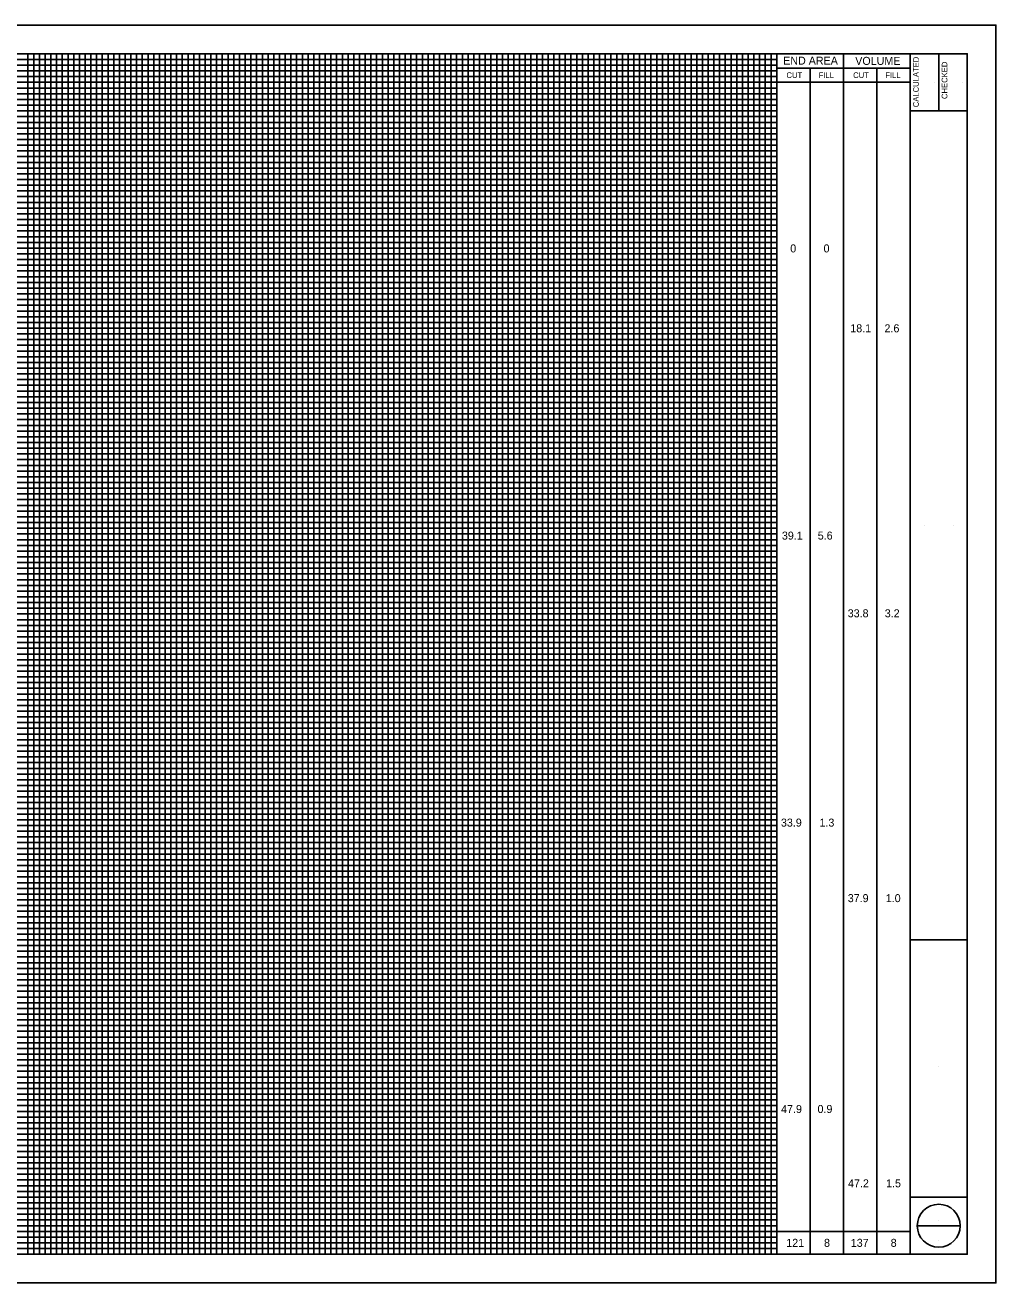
# Model space of a CAD drawing. Extents: x 2267521 to 2268201, y 655023 to 655463.
# Drawn here: x 2267861.3 to 2268201, y 655023.4 to 655463.4 of the extents above; entities that cross this region are included whole.
import ezdxf

# ---------------------------------------------------------------- set-up
doc = ezdxf.new("R2010")
doc.units = 0
for name, color, linetype in [('SH_Border', 7, 'Continuous'), ('SH_Cut_Line', 7, 'Continuous'), ('SH_Data', 7, 'Continuous'), ('SH_Major_Grid_Line', 7, 'Continuous'), ('SH_Masking', 7, 'Continuous'), ('SH_Minor_Grid_Line', 7, 'Continuous'), ('SH_Text', 7, 'Continuous')]:
    doc.layers.add(name, color=color, linetype=linetype)

msp = doc.modelspace()

# ---------------------------------------------------------------- linework, layer by layer
at = {"layer": 'SH_Border'}
for p, q in [((2268170.96, 655033.36), (2268170.96, 655453.36)), ((2268180.96, 655453.36), (2268180.96, 655433.36)), ((2268170.96, 655433.36), (2268190.96, 655433.36)), ((2268170.96, 655143.36), (2268190.96, 655143.36)), ((2268170.96, 655053.36), (2268190.96, 655053.36))]:
    msp.add_line(p, q, dxfattribs=at)
msp.add_lwpolyline([(2267560.96, 655453.36), (2268190.96, 655453.36), (2268190.96, 655033.36), (2267560.96, 655033.36)], close=True, dxfattribs=at)
at = {"layer": 'SH_Cut_Line'}
msp.add_lwpolyline([(2267520.96, 655023.36), (2268200.96, 655023.36), (2268200.96, 655463.36), (2267520.96, 655463.36)], close=True, dxfattribs=at)
at = {"layer": 'SH_Data'}
for p, q in [((2268124.29, 655033.36), (2268124.29, 655453.36)), ((2268147.63, 655033.36), (2268147.63, 655453.36)), ((2268124.29, 655448.36), (2268170.96, 655448.36)), ((2268135.96, 655033.36), (2268135.96, 655448.36)), ((2268159.3, 655033.36), (2268159.3, 655448.36)), ((2268124.29, 655443.36), (2268170.96, 655443.36)), ((2268179.36, 655443.43), (2268179.36, 655443.43)), ((2268189.36, 655443.43), (2268189.36, 655443.43)), ((2268175.96, 655288.36), (2268175.96, 655288.36)), ((2268186, 655288.36), (2268186, 655288.36)), ((2268180.96, 655099.2), (2268180.96, 655099.2)), ((2268124.29, 655041.36), (2268170.96, 655041.36)), ((2268173.46, 655043.36), (2268188.46, 655043.36)), ((2268180.96, 655045.06), (2268180.96, 655045.06)), ((2268130.13, 655037.36), (2268130.13, 655037.36)), ((2268141.8, 655037.36), (2268141.8, 655037.36)), ((2268153.46, 655037.36), (2268153.46, 655037.36)), ((2268165.13, 655037.36), (2268165.13, 655037.36)), ((2268180.96, 655038.26), (2268180.96, 655038.26))]:
    msp.add_line(p, q, dxfattribs=at)
msp.add_circle((2268180.96, 655043.36), 7.5, dxfattribs=at)
at = {"layer": 'SH_Major_Grid_Line'}
for p, q in [((2267864.29, 655033.36), (2267864.29, 655453.36)), ((2267884.29, 655033.36), (2267884.29, 655453.36)), ((2267904.29, 655033.36), (2267904.29, 655453.36)), ((2267924.29, 655033.36), (2267924.29, 655453.36)), ((2267944.29, 655033.36), (2267944.29, 655453.36)), ((2267964.29, 655033.36), (2267964.29, 655453.36)), ((2267984.29, 655033.36), (2267984.29, 655453.36)), ((2268004.29, 655033.36), (2268004.29, 655453.36)), ((2268024.29, 655033.36), (2268024.29, 655453.36)), ((2268044.29, 655033.36), (2268044.29, 655453.36)), ((2268064.29, 655033.36), (2268064.29, 655453.36)), ((2268084.29, 655033.36), (2268084.29, 655453.36)), ((2268104.29, 655033.36), (2268104.29, 655453.36)), ((2267584.29, 655433.36), (2268124.29, 655433.36)), ((2267584.29, 655413.36), (2268124.29, 655413.36)), ((2267584.29, 655393.36), (2268124.29, 655393.36)), ((2267584.29, 655373.36), (2268124.29, 655373.36)), ((2267584.29, 655353.36), (2268124.29, 655353.36)), ((2267584.29, 655333.36), (2268124.29, 655333.36)), ((2267584.29, 655313.36), (2268124.29, 655313.36)), ((2267584.29, 655293.36), (2268124.29, 655293.36)), ((2267584.29, 655273.36), (2268124.29, 655273.36)), ((2267584.29, 655253.36), (2268124.29, 655253.36)), ((2267584.29, 655233.36), (2268124.29, 655233.36)), ((2267584.29, 655213.36), (2268124.29, 655213.36)), ((2267584.29, 655193.36), (2268124.29, 655193.36)), ((2267584.29, 655173.36), (2268124.29, 655173.36)), ((2267584.29, 655153.36), (2268124.29, 655153.36)), ((2267584.29, 655133.36), (2268124.29, 655133.36)), ((2267584.29, 655113.36), (2268124.29, 655113.36)), ((2267584.29, 655093.36), (2268124.29, 655093.36)), ((2267584.29, 655073.36), (2268124.29, 655073.36)), ((2267584.29, 655053.36), (2268124.29, 655053.36))]:
    msp.add_line(p, q, dxfattribs=at)
at = {"layer": 'SH_Masking'}
msp.add_lwpolyline([(2267584.29, 655033.36), (2268124.29, 655033.36), (2268124.29, 655453.36), (2267584.29, 655453.36)], close=True, dxfattribs=at)
at = {"layer": 'SH_Minor_Grid_Line'}
for p, q in [((2267584.29, 655451.36), (2268124.29, 655451.36)), ((2267862.29, 655033.36), (2267862.29, 655453.36)), ((2267866.29, 655033.36), (2267866.29, 655453.36)), ((2267868.29, 655033.36), (2267868.29, 655453.36)), ((2267870.29, 655033.36), (2267870.29, 655453.36)), ((2267872.29, 655033.36), (2267872.29, 655453.36)), ((2267874.29, 655033.36), (2267874.29, 655453.36)), ((2267876.29, 655033.36), (2267876.29, 655453.36)), ((2267878.29, 655033.36), (2267878.29, 655453.36)), ((2267880.29, 655033.36), (2267880.29, 655453.36)), ((2267882.29, 655033.36), (2267882.29, 655453.36)), ((2267886.29, 655033.36), (2267886.29, 655453.36)), ((2267888.29, 655033.36), (2267888.29, 655453.36)), ((2267890.29, 655033.36), (2267890.29, 655453.36)), ((2267892.29, 655033.36), (2267892.29, 655453.36)), ((2267894.29, 655033.36), (2267894.29, 655453.36)), ((2267896.29, 655033.36), (2267896.29, 655453.36)), ((2267898.29, 655033.36), (2267898.29, 655453.36)), ((2267900.29, 655033.36), (2267900.29, 655453.36)), ((2267902.29, 655033.36), (2267902.29, 655453.36)), ((2267906.29, 655033.36), (2267906.29, 655453.36)), ((2267908.29, 655033.36), (2267908.29, 655453.36)), ((2267910.29, 655033.36), (2267910.29, 655453.36)), ((2267912.29, 655033.36), (2267912.29, 655453.36)), ((2267914.29, 655033.36), (2267914.29, 655453.36)), ((2267916.29, 655033.36), (2267916.29, 655453.36)), ((2267918.29, 655033.36), (2267918.29, 655453.36)), ((2267920.29, 655033.36), (2267920.29, 655453.36)), ((2267922.29, 655033.36), (2267922.29, 655453.36)), ((2267926.29, 655033.36), (2267926.29, 655453.36)), ((2267928.29, 655033.36), (2267928.29, 655453.36)), ((2267930.29, 655033.36), (2267930.29, 655453.36)), ((2267932.29, 655033.36), (2267932.29, 655453.36)), ((2267934.29, 655033.36), (2267934.29, 655453.36)), ((2267936.29, 655033.36), (2267936.29, 655453.36)), ((2267938.29, 655033.36), (2267938.29, 655453.36)), ((2267940.29, 655033.36), (2267940.29, 655453.36)), ((2267942.29, 655033.36), (2267942.29, 655453.36)), ((2267946.29, 655033.36), (2267946.29, 655453.36)), ((2267948.29, 655033.36), (2267948.29, 655453.36)), ((2267950.29, 655033.36), (2267950.29, 655453.36)), ((2267952.29, 655033.36), (2267952.29, 655453.36)), ((2267954.29, 655033.36), (2267954.29, 655453.36)), ((2267956.29, 655033.36), (2267956.29, 655453.36)), ((2267958.29, 655033.36), (2267958.29, 655453.36)), ((2267960.29, 655033.36), (2267960.29, 655453.36)), ((2267962.29, 655033.36), (2267962.29, 655453.36)), ((2267966.29, 655033.36), (2267966.29, 655453.36)), ((2267968.29, 655033.36), (2267968.29, 655453.36)), ((2267970.29, 655033.36), (2267970.29, 655453.36)), ((2267972.29, 655033.36), (2267972.29, 655453.36)), ((2267974.29, 655033.36), (2267974.29, 655453.36)), ((2267976.29, 655033.36), (2267976.29, 655453.36)), ((2267978.29, 655033.36), (2267978.29, 655453.36)), ((2267980.29, 655033.36), (2267980.29, 655453.36)), ((2267982.29, 655033.36), (2267982.29, 655453.36)), ((2267986.29, 655033.36), (2267986.29, 655453.36)), ((2267988.29, 655033.36), (2267988.29, 655453.36)), ((2267990.29, 655033.36), (2267990.29, 655453.36)), ((2267992.29, 655033.36), (2267992.29, 655453.36)), ((2267994.29, 655033.36), (2267994.29, 655453.36)), ((2267996.29, 655033.36), (2267996.29, 655453.36)), ((2267998.29, 655033.36), (2267998.29, 655453.36)), ((2268000.29, 655033.36), (2268000.29, 655453.36)), ((2268002.29, 655033.36), (2268002.29, 655453.36)), ((2268006.29, 655033.36), (2268006.29, 655453.36)), ((2268008.29, 655033.36), (2268008.29, 655453.36)), ((2268010.29, 655033.36), (2268010.29, 655453.36)), ((2268012.29, 655033.36), (2268012.29, 655453.36)), ((2268014.29, 655033.36), (2268014.29, 655453.36)), ((2268016.29, 655033.36), (2268016.29, 655453.36)), ((2268018.29, 655033.36), (2268018.29, 655453.36)), ((2268020.29, 655033.36), (2268020.29, 655453.36)), ((2268022.29, 655033.36), (2268022.29, 655453.36)), ((2268026.29, 655033.36), (2268026.29, 655453.36)), ((2268028.29, 655033.36), (2268028.29, 655453.36)), ((2268030.29, 655033.36), (2268030.29, 655453.36)), ((2268032.29, 655033.36), (2268032.29, 655453.36)), ((2268034.29, 655033.36), (2268034.29, 655453.36)), ((2268036.29, 655033.36), (2268036.29, 655453.36)), ((2268038.29, 655033.36), (2268038.29, 655453.36)), ((2268040.29, 655033.36), (2268040.29, 655453.36)), ((2268042.29, 655033.36), (2268042.29, 655453.36)), ((2268046.29, 655033.36), (2268046.29, 655453.36)), ((2268048.29, 655033.36), (2268048.29, 655453.36)), ((2268050.29, 655033.36), (2268050.29, 655453.36)), ((2268052.29, 655033.36), (2268052.29, 655453.36)), ((2268054.29, 655033.36), (2268054.29, 655453.36)), ((2268056.29, 655033.36), (2268056.29, 655453.36)), ((2268058.29, 655033.36), (2268058.29, 655453.36)), ((2268060.29, 655033.36), (2268060.29, 655453.36)), ((2268062.29, 655033.36), (2268062.29, 655453.36)), ((2268066.29, 655033.36), (2268066.29, 655453.36)), ((2268068.29, 655033.36), (2268068.29, 655453.36)), ((2268070.29, 655033.36), (2268070.29, 655453.36)), ((2268072.29, 655033.36), (2268072.29, 655453.36)), ((2268074.29, 655033.36), (2268074.29, 655453.36)), ((2268076.29, 655033.36), (2268076.29, 655453.36)), ((2268078.29, 655033.36), (2268078.29, 655453.36)), ((2268080.29, 655033.36), (2268080.29, 655453.36)), ((2268082.29, 655033.36), (2268082.29, 655453.36)), ((2268086.29, 655033.36), (2268086.29, 655453.36)), ((2268088.29, 655033.36), (2268088.29, 655453.36)), ((2268090.29, 655033.36), (2268090.29, 655453.36)), ((2268092.29, 655033.36), (2268092.29, 655453.36)), ((2268094.29, 655033.36), (2268094.29, 655453.36)), ((2268096.29, 655033.36), (2268096.29, 655453.36)), ((2268098.29, 655033.36), (2268098.29, 655453.36)), ((2268100.29, 655033.36), (2268100.29, 655453.36)), ((2268102.29, 655033.36), (2268102.29, 655453.36)), ((2268106.29, 655033.36), (2268106.29, 655453.36)), ((2268108.29, 655033.36), (2268108.29, 655453.36)), ((2268110.29, 655033.36), (2268110.29, 655453.36)), ((2268112.29, 655033.36), (2268112.29, 655453.36)), ((2268114.29, 655033.36), (2268114.29, 655453.36)), ((2268116.29, 655033.36), (2268116.29, 655453.36)), ((2268118.29, 655033.36), (2268118.29, 655453.36)), ((2268120.29, 655033.36), (2268120.29, 655453.36)), ((2268122.29, 655033.36), (2268122.29, 655453.36)), ((2267584.29, 655449.36), (2268124.29, 655449.36)), ((2267584.29, 655447.36), (2268124.29, 655447.36)), ((2267584.29, 655445.36), (2268124.29, 655445.36)), ((2267584.29, 655443.36), (2268124.29, 655443.36)), ((2267584.29, 655441.36), (2268124.29, 655441.36)), ((2267584.29, 655439.36), (2268124.29, 655439.36)), ((2267584.29, 655437.36), (2268124.29, 655437.36)), ((2267584.29, 655435.36), (2268124.29, 655435.36)), ((2267584.29, 655431.36), (2268124.29, 655431.36)), ((2267584.29, 655429.36), (2268124.29, 655429.36)), ((2267584.29, 655427.36), (2268124.29, 655427.36)), ((2267584.29, 655425.36), (2268124.29, 655425.36)), ((2267584.29, 655423.36), (2268124.29, 655423.36)), ((2267584.29, 655421.36), (2268124.29, 655421.36)), ((2267584.29, 655419.36), (2268124.29, 655419.36)), ((2267584.29, 655417.36), (2268124.29, 655417.36)), ((2267584.29, 655415.36), (2268124.29, 655415.36)), ((2267584.29, 655411.36), (2268124.29, 655411.36)), ((2267584.29, 655409.36), (2268124.29, 655409.36)), ((2267584.29, 655407.36), (2268124.29, 655407.36)), ((2267584.29, 655405.36), (2268124.29, 655405.36)), ((2267584.29, 655403.36), (2268124.29, 655403.36)), ((2267584.29, 655401.36), (2268124.29, 655401.36)), ((2267584.29, 655399.36), (2268124.29, 655399.36)), ((2267584.29, 655397.36), (2268124.29, 655397.36)), ((2267584.29, 655395.36), (2268124.29, 655395.36)), ((2267584.29, 655391.36), (2268124.29, 655391.36)), ((2267584.29, 655389.36), (2268124.29, 655389.36)), ((2267584.29, 655387.36), (2268124.29, 655387.36)), ((2267584.29, 655385.36), (2268124.29, 655385.36)), ((2267584.29, 655383.36), (2268124.29, 655383.36)), ((2267584.29, 655381.36), (2268124.29, 655381.36)), ((2267584.29, 655379.36), (2268124.29, 655379.36)), ((2267584.29, 655377.36), (2268124.29, 655377.36)), ((2267584.29, 655375.36), (2268124.29, 655375.36)), ((2267584.29, 655371.36), (2268124.29, 655371.36)), ((2267584.29, 655369.36), (2268124.29, 655369.36)), ((2267584.29, 655367.36), (2268124.29, 655367.36)), ((2267584.29, 655365.36), (2268124.29, 655365.36)), ((2267584.29, 655363.36), (2268124.29, 655363.36)), ((2267584.29, 655361.36), (2268124.29, 655361.36)), ((2267584.29, 655359.36), (2268124.29, 655359.36)), ((2267584.29, 655357.36), (2268124.29, 655357.36)), ((2267584.29, 655355.36), (2268124.29, 655355.36)), ((2267584.29, 655351.36), (2268124.29, 655351.36)), ((2267584.29, 655349.36), (2268124.29, 655349.36)), ((2267584.29, 655347.36), (2268124.29, 655347.36)), ((2267584.29, 655345.36), (2268124.29, 655345.36)), ((2267584.29, 655343.36), (2268124.29, 655343.36)), ((2267584.29, 655341.36), (2268124.29, 655341.36)), ((2267584.29, 655339.36), (2268124.29, 655339.36)), ((2267584.29, 655337.36), (2268124.29, 655337.36)), ((2267584.29, 655335.36), (2268124.29, 655335.36)), ((2267584.29, 655331.36), (2268124.29, 655331.36)), ((2267584.29, 655329.36), (2268124.29, 655329.36)), ((2267584.29, 655327.36), (2268124.29, 655327.36)), ((2267584.29, 655325.36), (2268124.29, 655325.36)), ((2267584.29, 655323.36), (2268124.29, 655323.36)), ((2267584.29, 655321.36), (2268124.29, 655321.36)), ((2267584.29, 655319.36), (2268124.29, 655319.36)), ((2267584.29, 655317.36), (2268124.29, 655317.36)), ((2267584.29, 655315.36), (2268124.29, 655315.36)), ((2267584.29, 655311.36), (2268124.29, 655311.36)), ((2267584.29, 655309.36), (2268124.29, 655309.36)), ((2267584.29, 655307.36), (2268124.29, 655307.36)), ((2267584.29, 655305.36), (2268124.29, 655305.36)), ((2267584.29, 655303.36), (2268124.29, 655303.36)), ((2267584.29, 655301.36), (2268124.29, 655301.36)), ((2267584.29, 655299.36), (2268124.29, 655299.36)), ((2267584.29, 655297.36), (2268124.29, 655297.36)), ((2267584.29, 655295.36), (2268124.29, 655295.36)), ((2267584.29, 655291.36), (2268124.29, 655291.36)), ((2267584.29, 655289.36), (2268124.29, 655289.36)), ((2267584.29, 655287.36), (2268124.29, 655287.36)), ((2267584.29, 655285.36), (2268124.29, 655285.36)), ((2267584.29, 655283.36), (2268124.29, 655283.36)), ((2267584.29, 655281.36), (2268124.29, 655281.36)), ((2267584.29, 655279.36), (2268124.29, 655279.36)), ((2267584.29, 655277.36), (2268124.29, 655277.36)), ((2267584.29, 655275.36), (2268124.29, 655275.36)), ((2267584.29, 655271.36), (2268124.29, 655271.36)), ((2267584.29, 655269.36), (2268124.29, 655269.36)), ((2267584.29, 655267.36), (2268124.29, 655267.36)), ((2267584.29, 655265.36), (2268124.29, 655265.36)), ((2267584.29, 655263.36), (2268124.29, 655263.36)), ((2267584.29, 655261.36), (2268124.29, 655261.36)), ((2267584.29, 655259.36), (2268124.29, 655259.36)), ((2267584.29, 655257.36), (2268124.29, 655257.36)), ((2267584.29, 655255.36), (2268124.29, 655255.36)), ((2267584.29, 655251.36), (2268124.29, 655251.36)), ((2267584.29, 655249.36), (2268124.29, 655249.36)), ((2267584.29, 655247.36), (2268124.29, 655247.36)), ((2267584.29, 655245.36), (2268124.29, 655245.36)), ((2267584.29, 655243.36), (2268124.29, 655243.36)), ((2267584.29, 655241.36), (2268124.29, 655241.36)), ((2267584.29, 655239.36), (2268124.29, 655239.36)), ((2267584.29, 655237.36), (2268124.29, 655237.36)), ((2267584.29, 655235.36), (2268124.29, 655235.36)), ((2267584.29, 655231.36), (2268124.29, 655231.36)), ((2267584.29, 655229.36), (2268124.29, 655229.36)), ((2267584.29, 655227.36), (2268124.29, 655227.36)), ((2267584.29, 655225.36), (2268124.29, 655225.36)), ((2267584.29, 655223.36), (2268124.29, 655223.36)), ((2267584.29, 655221.36), (2268124.29, 655221.36)), ((2267584.29, 655219.36), (2268124.29, 655219.36)), ((2267584.29, 655217.36), (2268124.29, 655217.36)), ((2267584.29, 655215.36), (2268124.29, 655215.36)), ((2267584.29, 655211.36), (2268124.29, 655211.36)), ((2267584.29, 655209.36), (2268124.29, 655209.36)), ((2267584.29, 655207.36), (2268124.29, 655207.36)), ((2267584.29, 655205.36), (2268124.29, 655205.36)), ((2267584.29, 655203.36), (2268124.29, 655203.36)), ((2267584.29, 655201.36), (2268124.29, 655201.36)), ((2267584.29, 655199.36), (2268124.29, 655199.36)), ((2267584.29, 655197.36), (2268124.29, 655197.36)), ((2267584.29, 655195.36), (2268124.29, 655195.36)), ((2267584.29, 655191.36), (2268124.29, 655191.36)), ((2267584.29, 655189.36), (2268124.29, 655189.36)), ((2267584.29, 655187.36), (2268124.29, 655187.36)), ((2267584.29, 655185.36), (2268124.29, 655185.36)), ((2267584.29, 655183.36), (2268124.29, 655183.36)), ((2267584.29, 655181.36), (2268124.29, 655181.36)), ((2267584.29, 655179.36), (2268124.29, 655179.36)), ((2267584.29, 655177.36), (2268124.29, 655177.36)), ((2267584.29, 655175.36), (2268124.29, 655175.36)), ((2267584.29, 655171.36), (2268124.29, 655171.36)), ((2267584.29, 655169.36), (2268124.29, 655169.36)), ((2267584.29, 655167.36), (2268124.29, 655167.36)), ((2267584.29, 655165.36), (2268124.29, 655165.36)), ((2267584.29, 655163.36), (2268124.29, 655163.36)), ((2267584.29, 655161.36), (2268124.29, 655161.36)), ((2267584.29, 655159.36), (2268124.29, 655159.36)), ((2267584.29, 655157.36), (2268124.29, 655157.36)), ((2267584.29, 655155.36), (2268124.29, 655155.36)), ((2267584.29, 655151.36), (2268124.29, 655151.36)), ((2267584.29, 655149.36), (2268124.29, 655149.36)), ((2267584.29, 655147.36), (2268124.29, 655147.36)), ((2267584.29, 655145.36), (2268124.29, 655145.36)), ((2267584.29, 655143.36), (2268124.29, 655143.36)), ((2267584.29, 655141.36), (2268124.29, 655141.36)), ((2267584.29, 655139.36), (2268124.29, 655139.36)), ((2267584.29, 655137.36), (2268124.29, 655137.36)), ((2267584.29, 655135.36), (2268124.29, 655135.36)), ((2267584.29, 655131.36), (2268124.29, 655131.36)), ((2267584.29, 655129.36), (2268124.29, 655129.36)), ((2267584.29, 655127.36), (2268124.29, 655127.36)), ((2267584.29, 655125.36), (2268124.29, 655125.36)), ((2267584.29, 655123.36), (2268124.29, 655123.36)), ((2267584.29, 655121.36), (2268124.29, 655121.36)), ((2267584.29, 655119.36), (2268124.29, 655119.36)), ((2267584.29, 655117.36), (2268124.29, 655117.36)), ((2267584.29, 655115.36), (2268124.29, 655115.36)), ((2267584.29, 655111.36), (2268124.29, 655111.36)), ((2267584.29, 655109.36), (2268124.29, 655109.36)), ((2267584.29, 655107.36), (2268124.29, 655107.36)), ((2267584.29, 655105.36), (2268124.29, 655105.36)), ((2267584.29, 655103.36), (2268124.29, 655103.36)), ((2267584.29, 655101.36), (2268124.29, 655101.36)), ((2267584.29, 655099.36), (2268124.29, 655099.36)), ((2267584.29, 655097.36), (2268124.29, 655097.36)), ((2267584.29, 655095.36), (2268124.29, 655095.36)), ((2267584.29, 655091.36), (2268124.29, 655091.36)), ((2267584.29, 655089.36), (2268124.29, 655089.36)), ((2267584.29, 655087.36), (2268124.29, 655087.36)), ((2267584.29, 655085.36), (2268124.29, 655085.36)), ((2267584.29, 655083.36), (2268124.29, 655083.36)), ((2267584.29, 655081.36), (2268124.29, 655081.36)), ((2267584.29, 655079.36), (2268124.29, 655079.36)), ((2267584.29, 655077.36), (2268124.29, 655077.36)), ((2267584.29, 655075.36), (2268124.29, 655075.36)), ((2267584.29, 655071.36), (2268124.29, 655071.36)), ((2267584.29, 655069.36), (2268124.29, 655069.36)), ((2267584.29, 655067.36), (2268124.29, 655067.36)), ((2267584.29, 655065.36), (2268124.29, 655065.36)), ((2267584.29, 655063.36), (2268124.29, 655063.36)), ((2267584.29, 655061.36), (2268124.29, 655061.36)), ((2267584.29, 655059.36), (2268124.29, 655059.36)), ((2267584.29, 655057.36), (2268124.29, 655057.36)), ((2267584.29, 655055.36), (2268124.29, 655055.36)), ((2267584.29, 655051.36), (2268124.29, 655051.36)), ((2267584.29, 655049.36), (2268124.29, 655049.36)), ((2267584.29, 655047.36), (2268124.29, 655047.36)), ((2267584.29, 655045.36), (2268124.29, 655045.36)), ((2267584.29, 655043.36), (2268124.29, 655043.36)), ((2267584.29, 655041.36), (2268124.29, 655041.36)), ((2267584.29, 655039.36), (2268124.29, 655039.36)), ((2267584.29, 655037.36), (2268124.29, 655037.36)), ((2267584.29, 655035.36), (2268124.29, 655035.36))]:
    msp.add_line(p, q, dxfattribs=at)

# ---------------------------------------------------------------- texts
at = {"layer": 'SH_Data'}
for s, height, p in [('END AREA', 2.8, (2268126.54, 655449.55)), ('VOLUME', 2.8, (2268151.76, 655449.46)), ('CUT', 2, (2268127.7, 655444.86)), ('FILL', 2, (2268138.97, 655444.86)), ('CUT', 2, (2268151.03, 655444.86)), ('FILL', 2, (2268162.3, 655444.86))]:
    msp.add_text(s, height=height, dxfattribs=at).set_placement(p)
for s, p in [('CALCULATED', (2268174.01, 655434.65)), ('CHECKED', (2268184.01, 655437.52))]:
    msp.add_text(s, height=2, rotation=90, dxfattribs=at).set_placement(p)
at = {"layer": 'SH_Text'}
for s, p in [('0', (2268129.02, 655383.86)), ('0', (2268140.68, 655383.86)), ('18.1', (2268150.03, 655355.91)), ('2.6', (2268162, 655355.91)), ('39.1', (2268126.1, 655283.39)), ('5.6', (2268138.64, 655283.39)), ('33.8', (2268149.13, 655256.21)), ('3.2', (2268162.09, 655256.21)), ('33.9', (2268125.76, 655182.98)), ('1.3', (2268139.25, 655182.98)), ('37.9', (2268149.14, 655156.55)), ('1.0', (2268162.45, 655156.55)), ('47.9', (2268125.82, 655082.79)), ('0.9', (2268138.56, 655082.79)), ('47.2', (2268149.24, 655056.78)), ('1.5', (2268162.56, 655056.78)), ('121', (2268127.63, 655035.96)), ('8', (2268140.84, 655035.96)), ('137', (2268150.2, 655035.96)), ('8', (2268164.17, 655035.96))]:
    msp.add_text(s, height=2.8, dxfattribs=at).set_placement(p)

doc.saveas('drawing.dxf')
